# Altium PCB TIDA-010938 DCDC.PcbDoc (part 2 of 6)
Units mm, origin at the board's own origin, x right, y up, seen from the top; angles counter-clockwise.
Board outline 280 x 174.95 mm, 4 copper layers (Top Layer, Layer 1, Layer 2, Bottom Layer), stack 1.787 mm thick; 409 components, 218 nets, 1371 pads, 2268 vias.
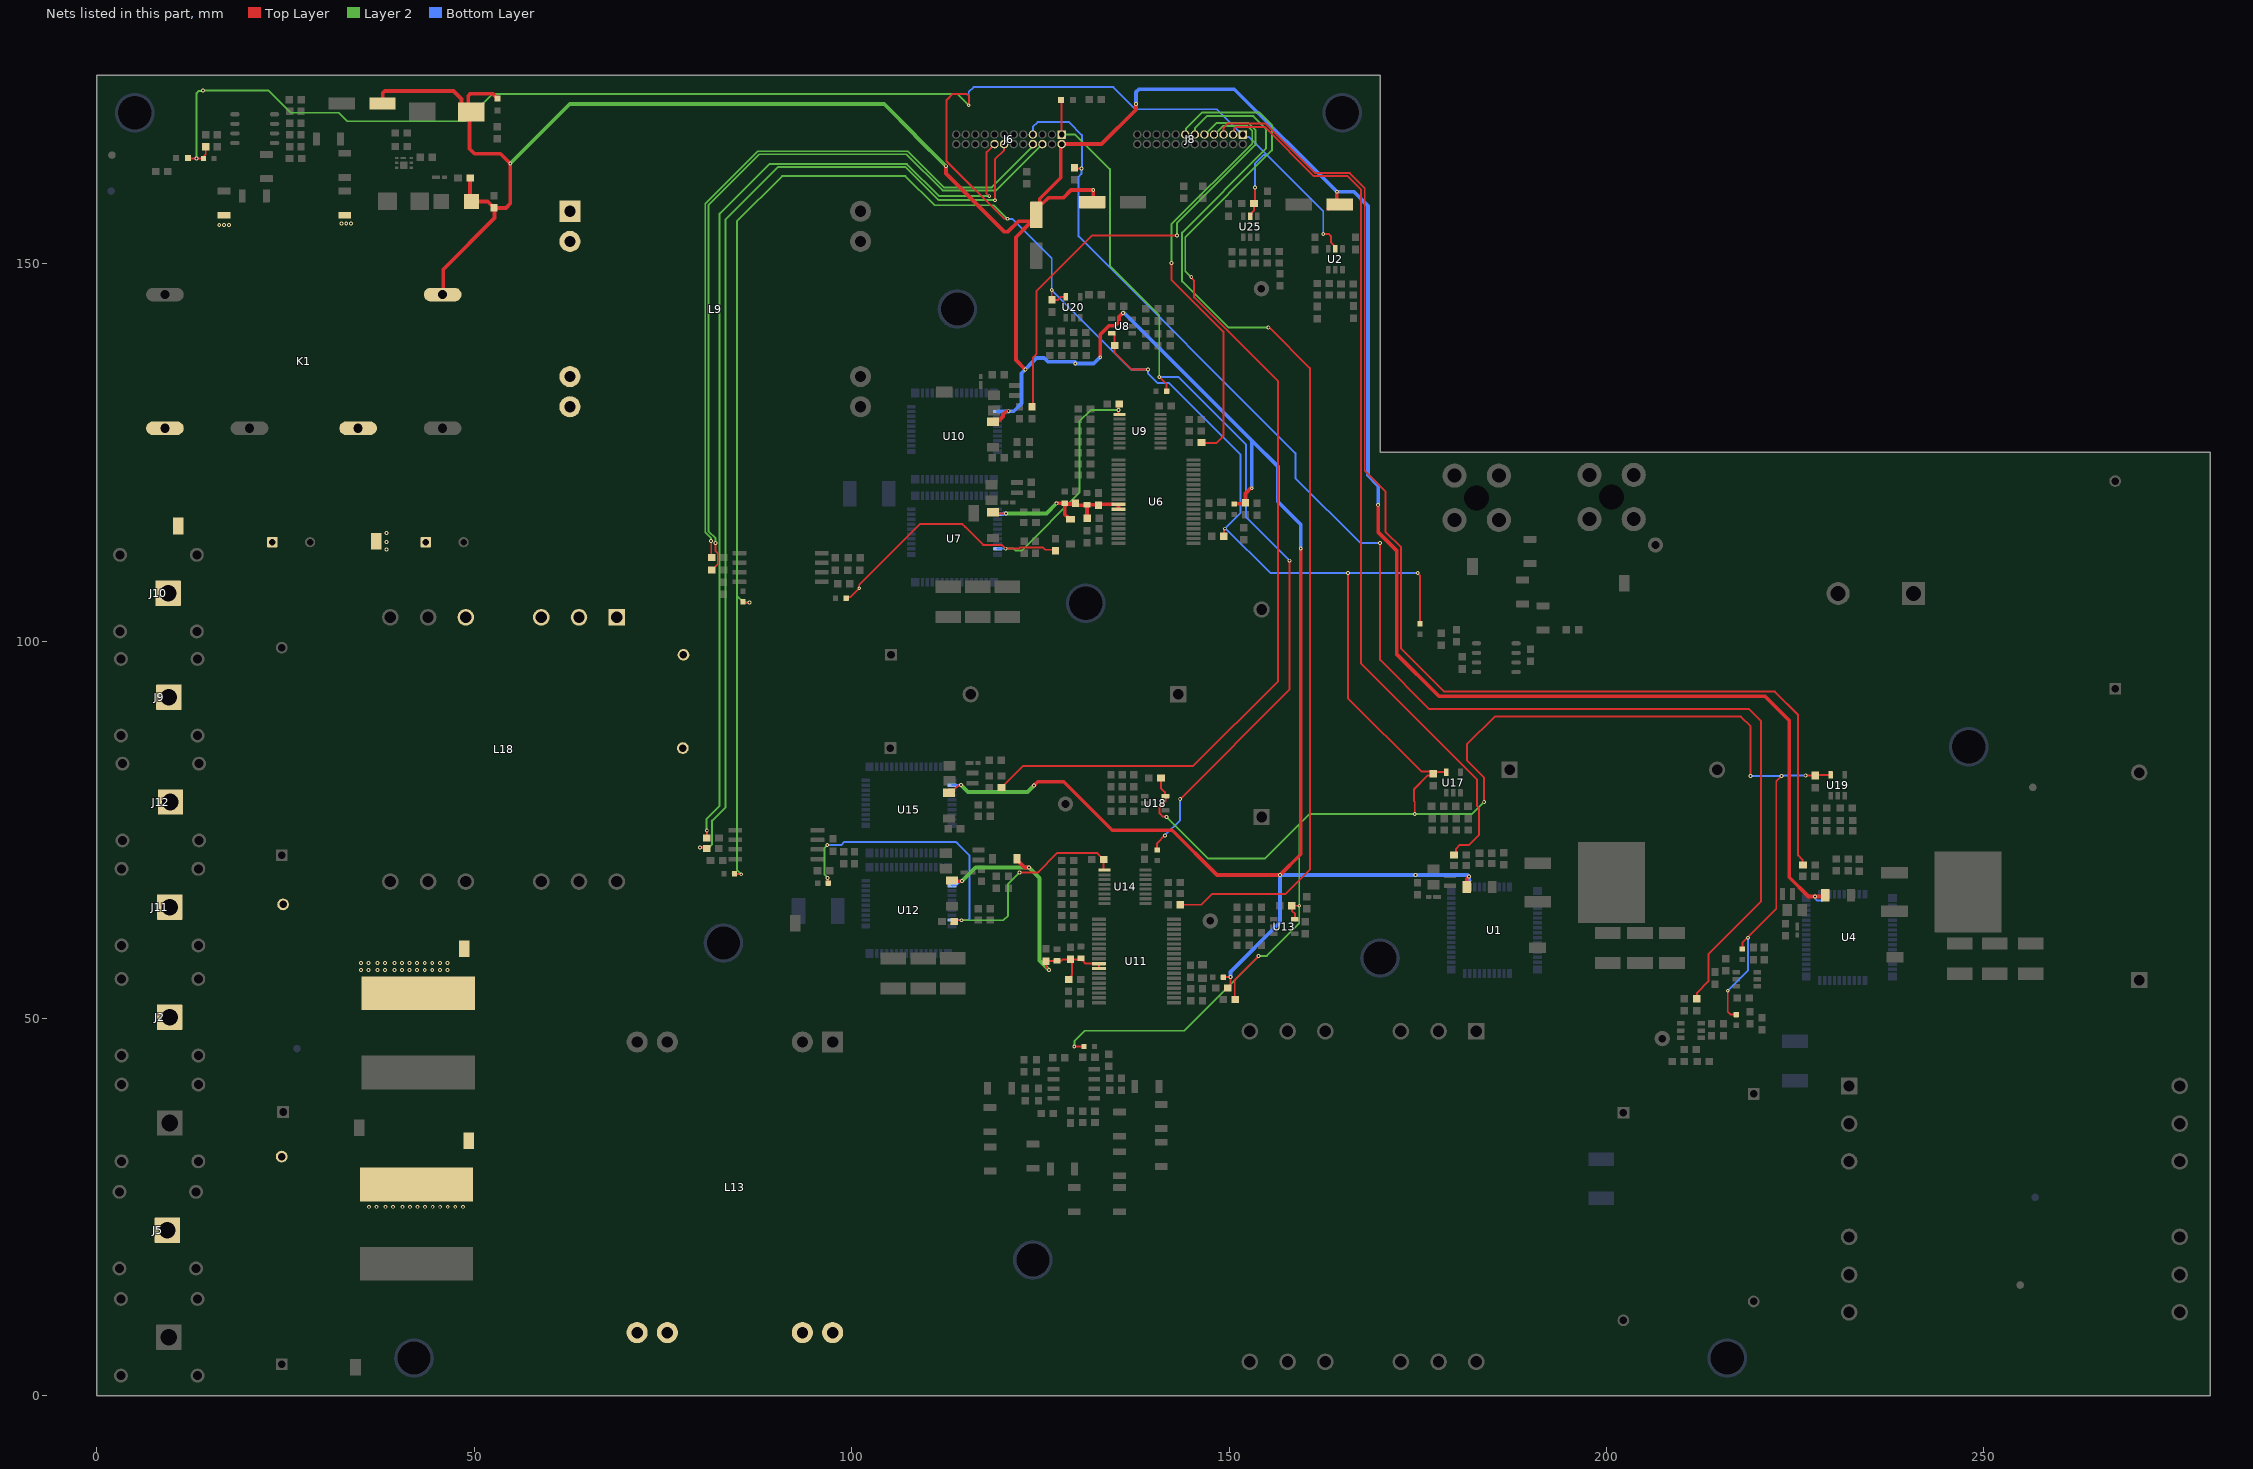
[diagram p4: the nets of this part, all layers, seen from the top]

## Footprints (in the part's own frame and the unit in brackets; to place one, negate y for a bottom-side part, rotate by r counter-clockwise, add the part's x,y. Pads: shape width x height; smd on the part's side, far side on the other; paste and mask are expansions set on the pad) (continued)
FP-CSS2H-2512K-3L00F_2512-MFG [mm]
  rrect6% 1.8x3.4 smd paste+0 mask+0: 1(-2.6,0) 2(2.6,0)
  silkscreen extent -1.33,-1.63 1.33,1.63, body extent -3.17,-1.53 3.17,1.53, height 0.81
FP-FCR7350B_CONN_BANANA_JACK-MFG [mm]
  rrect3% 3.35x3.35 hole 2.2 paste-2539.97 mask+0: 1(11,0)
  round 1.85 hole 1.2 paste-2539.97 mask+0: 2(4.64,5.08) 3(14.8,5.08) 4(4.64,-5.08) 5(14.8,-5.08)
  silkscreen extent 5.94,-6.05 17.2,6.05, body extent -16.7,-6.15 16.7,6.15, height 0.25
FP-FCR7350R_CONN_BANANA_JACK-MFG [mm]
  rrect3% 3.35x3.35 hole 2.2 paste-2539.97 mask+0: 1(11,0)
  round 1.85 hole 1.2 paste-2539.97 mask+0: 2(4.64,5.08) 3(14.8,5.08) 4(4.64,-5.08) 5(14.8,-5.08)
  silkscreen extent 5.94,-6 17.22,6, body extent -16.6,-6.1 16.6,6.1, height 0.25
"FP-G7L-2A-X DC12_PTH_RELAY_52MM5_35MM5-MFG" [mm]
  rrect100% 5x1.8 hole 1.2 slot 4.4 at 0 deg paste-1000 mask+0: 0(18.4,9.1) 1(-18.4,9.1) 2(18.4,-8.6) 4(7.2,-8.6) 6(-7.2,-8.6) 8(-18.4,-8.6)
  silkscreen extent -26.97,-17.75 26.25,17.75, body extent -26.35,-17.85 26.35,17.85, height 0.25
"FP-KG DELLS1.22-JGKH-24_0603-MFG" [mm]
  rrect20% 1.05x0.5 smd paste-1000 mask+0: 1(-0.47,0)
  rrect20% 0.7x0.5 smd paste-1000 mask+0: 2(0.645,0)
  silkscreen extent -1.67,-0.63 0.75,0.63, body extent -1.09,-0.55 1.09,0.55, height 0.25
FP-MH1608-601Y_0603-MFG [mm]
  rrect14% 0.7x0.7 smd paste+0 mask+0: 1(-0.7,0) 2(0.7,0)
  silkscreen extent -0.87,-0.8 0.87,0.8, body extent -1.15,-0.6 1.15,0.6, height 0.25
FP-PTCEL13R102SBE_RADIAL-MFG [mm]
  rrect7% 1.35x1.35 hole 0.85 paste-2539.97 mask+0: 1(-2.5,0)
  round 1.35 hole 0.85 paste-2539.97 mask+0: 2(2.5,0)
  silkscreen extent -6.75,-3.5 6.75,3.5, body extent -6.85,-3.6 6.85,3.6, height 0.25
FP-R533R456050P0M_RADIAL-MFG [mm]
  rrect6% 1.55x1.55 hole 1 paste-2539.97 mask+0: 1(-13.75,0)
  round 1.55 hole 1 paste-2539.97 mask+0: 2(13.75,0)
  silkscreen extent -16.25,-8.15 16.25,8.15, body extent -16.35,-8.25 16.35,8.25, height 0.25
FP-SDEM20161T-4R7MS_SMD2-MFG [mm]
  rrect15% 0.65x1.6 smd paste+0 mask+0: 1(-0.675,0) 2(0.675,0)
  silkscreen extent -1.05,-1.22 1.05,1.2, body extent -1.15,-0.95 1.15,0.95, height 0.25
FP-SHF-112-01-L-D-TH_HDR24-MFG [mm]
  rrect9% 1.12x1.12 hole 0.74 paste-2539.97 mask+0: 1(-6.985,-0.89)
  round 1.12 hole 0.74 paste-2539.97 mask+0: 2(-6.985,0.38) 3(-5.715,-0.89) 4(-5.715,0.38) 5(-4.445,-0.89) 6(-4.445,0.38) 7(-3.175,-0.89) 8(-3.175,0.38) 9(-1.905,-0.89) 10(-1.905,0.38) 11(-0.635,-0.89) 12(-0.635,0.38) 13(0.635,-0.89) 14(0.635,0.38) 15(1.905,-0.89) 16(1.905,0.38) 17(3.175,-0.89) 18(3.175,0.38) 19(4.445,-0.89) 20(4.445,0.38) 21(5.715,-0.89) 22(5.715,0.38) 23(6.985,-0.89) 24(6.985,0.38)
  silkscreen extent -10.86,-3.46 10.86,2.86, body extent -10.96,-2.96 10.96,2.96, height 0.25
FP-SMBJ5350B-TP_SMB-MFG [mm]
  rrect4% 2.5x2.3 smd paste+0 mask+0: 1(-2.15,0) 2(2.15,0)
  silkscreen extent -4.12,-1.97 2.42,1.97, body extent -3.5,-2.07 3.5,2.07, height 0.25
FP-SRP1513CA-220M_SMD2-MFG [mm]
  rrect2% 4.5x15 smd paste+0 mask+0: 1(-5.25,0) 2(5.25,0)
  silkscreen extent -7.9,-8.4 7.9,8.4, body extent -8,-8.5 8,8.5, height 0.25
FP-ZRB18AR61E106ME01L_0603-MFG [mm]
  rrect13% 0.75x0.9 smd paste+0 mask+0: 1(-0.775,0) 2(0.775,0)
  silkscreen extent 0,-0.5 0,0.5, body extent -1.25,-0.6 1.25,0.6, height 0.25
Harwin_S2751-46R [mm] "Test Point, SMT"
  rect 2.2x1.4 smd: 1(0,0)
  body extent -1,-0.6 1,0.6, height 1.4
IEC_HighVoltage_Small [mm]
  silkscreen extent -2.72,-2.24 2.72,2.47
IEC_HotSurface_Small [mm]
  silkscreen extent -2.72,-2.36 2.72,2.35
Keystone5001 [mil] "For Keystone 500x miniature loop terminals"
  round 80 hole 40: 1(0,0)
  silkscreen extent -52,-52 52,52, body extent -49,-49 49,49, height 182
Label_650x200 [mil] "Thermal Transfer Label"
  round 1 on Mech13: 0(0,0)
  silkscreen extent -325,-100 325,100, body extent -325,-100 325,100, height 1
RQS0052C-C01-MFG [mm]
  rrect9% 1.15x1.1 smd paste+0 mask+0: 1(-5.725,5.2) 16(-5.725,-5.2) 27(5.725,-5.2) 42(5.725,5.2)
  rrect22% 1.15x0.45 smd paste+0 mask+0: 2(-5.725,4.225) 3(-5.725,3.575) 4(-5.725,2.925) 5(-5.725,2.275) 6(-5.725,1.625) 7(-5.725,0.975) 8(-5.725,0.325) 9(-5.725,-0.325) 10(-5.725,-0.975) 11(-5.725,-1.625) 12(-5.725,-2.275) 13(-5.725,-2.925) 14(-5.725,-3.575) 15(-5.725,-4.225) 28(5.725,-4.225) 29(5.725,-3.575) 30(5.725,-2.925) 31(5.725,-2.275) 32(5.725,-1.625) 33(5.725,-0.975) 34(5.725,-0.325) 35(5.725,0.325) 36(5.725,0.975) 37(5.725,1.625) 38(5.725,2.275) 39(5.725,2.925) 40(5.725,3.575) 41(5.725,4.225)
  rrect15% 0.665x1.15 smd paste+0 mask+0: 17(-2.043,-5.725) 52(-2.043,5.725)
  rrect22% 0.45x1.15 smd paste+0 mask+0: 18(-1.285,-5.725) 19(-0.635,-5.725) 20(0.015,-5.725) 21(0.665,-5.725) 22(1.315,-5.725) 23(1.965,-5.725) 24(2.615,-5.725) 25(3.265,-5.725) 26(3.915,-5.725) 43(3.915,5.725) 44(3.265,5.725) 45(2.615,5.725) 46(1.965,5.725) 47(1.315,5.725) 48(0.665,5.725) 49(0.015,5.725) 50(-0.635,5.725) 51(-1.285,5.725)
  silkscreen extent -7.02,-6.05 4.77,6.05, body extent -6,-6 6,6, height 1
SM_RADIAL_8MM [mm] "Nichicon 8x10"
  rect 3.5x2.5 smd: 1(-3.25,0) 2(3.25,0)
  silkscreen extent -4.25,-4.25 4.25,4.25, body extent -4.25,-4.25 4.25,4.25, height 10.5
SMA [mm] "Molded Diode, 2-Leads, Body 4.3x2.6mm, IPC Medium Density, based on OnSemi component dimensions and land pattern"
  rect 2x2 smd: 1(-2,0) 2(2,0)
  silkscreen extent -3.66,-1.57 2.79,1.58, body extent -2.6,-1.3 2.6,1.3, height 2.42
SOD-123 [mm] "On Semi recommended land pattern"
  rect 0.915x1.22 smd: 1(-1.637,0) 2(1.637,0)
  silkscreen extent -2.74,-1.17 2.03,1.17, body extent -1.93,-0.9 1.93,0.9, height 1.35
TNPV1206 [mm] "VISHAY"
  rrect11% 0.9x1.7 smd: 1(-1.6,0) 2(1.6,0)
  silkscreen extent -2.4,-1.2 2.4,1.2, body extent -1.67,-0.87 1.67,0.87, height 0.65
UWT_630x770 [mm] "SMD, 2-Leads, Dia 6.3mm"
  rrect6% 3.5x1.6 smd: 1(-2.7,0) 2(2.7,0)
  body extent -3.5,-3.3 3.5,3.3, height 8
WEEE_Minimum [mm] "WEEElie bin"
  silkscreen extent -2.42,-4.38 2.52,2.65
WL-SMCW_GREEN [mm] "WURTH"
  rect 0.8x0.8 smd: 1(-0.8,0) 2(0.8,0)
  silkscreen extent -1.9,-0.8 1.2,0.8, body extent -0.85,-0.45 0.85,0.45, height 0.8
Wurth_WP-THRBU [mm] "Power Element Bush, M3, TH"
  round 3.2 hole 1.85: 1(-2.935,-2.935) 1(-2.935,2.935) 1(2.935,-2.935) 1(2.935,2.935)
  round 3.1 on Top Paste: ""(-2.935,-2.935) ""(-2.935,2.935) ""(2.935,-2.935) ""(2.935,2.935)
  round 3 hole 3.3 unplated mask+0.102: ""(0,0)
  silkscreen extent -3.5,-3.5 3.5,3.5, body extent -3.5,-3.5 3.5,3.5, height 3

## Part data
C1 C8 C21 C31 C36 C37 C43 C48 C49 C50 C51 C52 C56 C57 C61 C70 C71 C77 C84 C85 C95 C102 C107 C108 C119 C124 C125 C128 C129 C132 C146 C155: library part CMP-0006752-5, "CAP, CERM, 0.1 uF, 25 V, +/- 5%, X7R, 0603", Cap_Case=0603, Manufacturer=AVX, Supplier Part Number 1=478-3713-1-ND, TempCo=X7R, Tolerance_%=5%, Value1="0.05 ohm", Value2=25V, ValueDisplayed=0.1uF
C2 C30 C224: library part CMP-0045188-1, "5.6 µF Film Capacitor 310V 630V Polypropylene (PP), Metallized Radial", Digikey Part Number=399-R533R456050P0M-ND, Manufacturer=KEMET, Mouser Part Number=80-R533R456050P0M, Operating Temperature Range="-40°C to +110°C", Tolerance_%=20%, ValueDisplayed=5.6uF, Voltage Ac Rating X=310V
C3 C4 C10 C24: library part CMP-0045062-1, "2.7 µF Film Capacitor 900V Polypropylene (PP), Metallized Radial", Digikey Part Number=399-C4AKOBU4270A3YJ-ND, Manufacturer=Kemet, Mouser Part Number=80-C4AKOBU4270A3YJ, Operating Temperature Range="-55°C to +135°C", Tolerance_%=5%, ValueDisplayed=2.7uF
C5 C115 C121 C144: library part CMP-0081462-1, "CAP, AL, 100 µF, 25 V, +/- 20%, SMD", Cap_Case=6.3x7.7mm, Manufacturer=Nichicon, Supplier Part Number 1=493-2190-1-ND, Tolerance_%=20%, Value2=25V, ValueDisplayed=100µF
C6 C20 C34 C59 C68 C93: library part CMP-0750154-1, "CAP, CERM, 10 µF, 25 V,+/- 10%, X7R, AEC-Q200 Grade 1, 1206", Cap_Case=1206, Manufacturer="Taiyo Yuden", TempCo=X7R, Tolerance_%=10%, Value2=25V, ValueDisplayed=10µF
C7 C11 C12 C14 C15 C19 C22 C25 C26 C28 C29 C35 C45 C54 C55 C58 C62 C64 C69 C79 C88 C89 C90 C92 C96 C98 C112 C116 C118 C120 C122 C142 C151 C152: library part CMP-0007442-5, "CAP, CERM, 220 pF, 50 V, +/- 10%, X7R, 0603", Cap_Case=0603, Manufacturer=MuRata, Supplier Part Number 1=490-1483-1-ND, TempCo=X7R, Tolerance_%=10%, Value1=Unknown, Value2=50V, ValueDisplayed=220pF
C9 C23: library part CMP-0045101-1, "6 µF Film Capacitor 700V Polypropylene (PP), Metallized Radial", Digikey Part Number=399-C4AUJBU4600M18J-ND, Manufacturer=KEMET, Mouser Part Number=80-C4AUJBU4600M18J, Operating Temperature Range="-55°C to +105°C", Tolerance_%=5%, ValueDisplayed=6uF
C13 C27 C46 C65 C80 C99: library part CMP-0007975-2, "CAP, CERM, 2.2 uF, 25 V, +/- 10%, X7R, AEC-Q200 Grade 1, 0805", Cap_Case=0805, Manufacturer=TDK, Supplier Part Number 1=445-6965-1-ND, TempCo=X7R, Tolerance_%=10%, Value1=Unknown, Value2=25V, ValueDisplayed=2.2uF
C16: library part CMP-0007470-5, "CAP, CERM, 0.1 uF, 100 V, +/- 10%, X7R, 0603", Cap_Case=0603, Manufacturer=MuRata, Supplier Part Number 1=490-6439-1-ND, TempCo=X7R, Tolerance_%=10%, Value1=Unknown, Value2=100V, ValueDisplayed=0.1uF
C17 C32 C38 C72: library part CMP-0086152-1, "CAP, CERM, 1 µF, 25 V,+/- 10%, X5R, 0603", Cap_Case=0603, Manufacturer="Taiyo Yuden", TempCo=X5R, Tolerance_%=10%, Value2=25V, ValueDisplayed=1µF
C18 C33 C44 C47 C53 C81: library part CMP-0750039-1, "CAP, CERM, 0.01 µF, 50 V,+/- 10%, X7R, 0603", Cap_Case=0603, Manufacturer="Wurth Elektronik", TempCo=X7R, Tolerance_%=10%, Value2=50V, ValueDisplayed=0.01µF
C39 C73: library part CMP-0009474-2, "CAP, CERM, 20 uF, 16 V, +/- 20%, X5R, 0704", Cap_Case=0704, Manufacturer=MuRata, TempCo=X5R, Tolerance_%=20%, Value1=Unknown, Value2=16V, ValueDisplayed=20uF
C40 C41 C74 C75: library part CMP-0094458-1, "10µF ±20% 25V Ceramic Capacitor X5R 0603 (1608 Metric)", Digikey Part Number=490-10991-1-ND, Manufacturer="Murata Electronics", Mouser Part Number=81-ZRB18AR61E106ME1L, Operating Temperature Range="-55°C to +85°C", Temperature Characteristic=X5R, Tolerance_%=20%, ValueDisplayed=10uF
C42 C76: library part CMP-0007209-4, "CAP, CERM, 330 pF, 50 V, +/- 5%, C0G/NP0, 0603", Cap_Case=0603, Manufacturer=MuRata, Supplier Part Number 1=490-1439-1-ND, TempCo=C0G/NP0, Tolerance_%=5%, Value1=Unknown, Value2=50V, ValueDisplayed=330pF
C60 C94: library part CMP-0045063-1, "2.4 µF Film Capacitor 700V Polypropylene (PP), Metallized Radial", Digikey Part Number=399-C4AUJBU4240M1WJ-ND, Manufacturer=KEMET, Mouser Part Number=80-C4AUJBU4240M1WJ, Operating Temperature Range="-55°C to +105°C", Tolerance_%=5%, ValueDisplayed=2.4uF
C63 C66 C103 C104 C105 C109 C123: library part CMP-0007189-4, "CAP, CERM, 1600 pF, 50 V, +/- 5%, C0G/NP0, 0603", Cap_Case=0603, Manufacturer=MuRata, Supplier Part Number 1=490-1456-1-ND, TempCo=C0G/NP0, Tolerance_%=5%, Value1=Unknown, Value2=50V, ValueDisplayed=1600pF
C67 C78 C82 C83 C86 C87 C91 C97: library part CMP-0006920-4, "CAP, CERM, 330 pF, 50 V, +/- 5%, C0G/NP0, 0603", Cap_Case=0603, Manufacturer=Kemet, Supplier Part Number 1=399-1068-1-ND, TempCo=C0G/NP0, Tolerance_%=5%, Value1=Unknown, Value2=50V, ValueDisplayed=330pF
C100 C101 C106 C110 C111 C113 C127 C130 C131 C135 C140 C141: library part CMP-0009326-2, "0.03 µF ±10% 1000V (1kV) Ceramic Capacitor C0G, NP0 1812 (4532 Metric)", Cap_Case=1812, Manufacturer=Kemet, Supplier Part Number 1=399-C1812C303KDGLCAUTOTR-ND, TempCo=NP0, Tolerance_%=10%, Value1=Unknown, Value2=1000V, ValueDisplayed=0.03uF
C114: library part CMP-0033686-1, "ALH82, Aluminum Electrolytic, 160 uF, 20%, 600 VDC, -40/+105°C", Leakage Current=288uA, Manufacturer=KEMET, Operating Temperature Range="-40°C to +105°C", Tolerance_%=20%, ValueDisplayed=160uF
C117: library part CMP-0012113-3, "CAP, Aluminum Polymer, 10 uF, 25 V, +/- 20%, 0.06 ohm, 8x10 SMD", Cap_Case=8.3x8.3x6.9, Manufacturer=Panasonic, Tolerance_%=20%, Value1="0.06 ohm", Value2=25V, ValueDisplayed=10uF
C143: library part CMP-0123402-1, "15 µF Film Capacitor 600V Polypropylene (PP), Metallized Radial", Digikey Part Number=399-C4AQHBU5150P12J-ND, Manufacturer=KEMET, Mouser Part Number=80-C4AQHBU5150P12J, Operating Temperature Range="-55°C to +125°C", Tolerance_%=5%, ValueDisplayed=15uF
D1 D3: library part CMP-0042032-1, "Schottky Diode 650 V 20A Surface Mount TO-263-2", Digikey Part Number=1697-C6D20065G-ND, Forward Current=64A, Manufacturer=Wolfspeed, Max Surge Forward Current=135A, Mouser Part Number=941-C6D20065G, Operating Temperature Range="-55°C to +175°C", Peak Reverse Current=5uA, ValueDisplayed=1153pF
D6 D9: library part CMP-0005769-4, "Diode, Zener, 16 V, 500 mW, AEC-Q101, SOD-123", Manufacturer="Diodes Inc.", Power_W=500mW, Value1=0.5W
D11: library part CMP-0097215-1, "Zener Diode 13 V 5 W ±5% Surface Mount DO-214AA (SMB)", Digikey Part Number=SMBJ5350B-TPMSCT-ND, Manufacturer=MCC, Max Reverse Leakage Current=1uA, Mouser Part Number=833-SMBJ5350B-TP, Operating Temperature Range="-55°C to +150°C", Power_W=5W
D12: library part CMP-0029023-2, "Diode, Superfast Rectifier, 150 V, 1 A, SMA", Manufacturer="Diodes Inc.", Value1=1A, Value2=0.92V
D13 D15 D16: library part CMP-0002894-2, "LED, Green, SMD", Color=green, Manufacturer="Wurth Elektronik", Value1=W, Value2=2V
D14 D17 D18 D19 D20 D21 D22: library part CMP-0093310-1, "Standard LEDs - SMD Green TOPLED E 1608", Color=Green, Forward Current=2mA, Manufacturer="Osram Opto", Mouser Part Number=720-KGDELLS122A4849, Operating Temperature Range="-40°C to +110°C"
FB1 FB2 FB3 FB4 FB5 FB6 FB7 FB9 FB10 FB11 FB12 FB13 FB14: library part CMP-0037505-1, "600 Ohms @ 100 MHz 1 Power, Signal Line Ferrite Bead 0603 (1608 Metric) 1A 200mOhm", Digikey Part Number=MH1608-601YCT-ND, Impedance At Frequency="600Ω @ 100MHz", Manufacturer=Bourns, Mouser Part Number=652-MH1608-601Y, Operating Temperature Range="-55°C to +125°C", Test Frequency=100MHz, Tolerance_%=25%
FID1 FID2 FID3 FID4 FID5 FID6: library part CMP-0077181-1, "Fiducial mark.  There is nothing to buy or mount.", Manufacturer=N/A
J1 J4: library part CMP-0078526-1, "Power Element Bush, M3, TH", Current_A=50A, Manufacturer="Wurth Elektronik", Supplier Part Number 1=732-10882-1-ND
J2 J5 J9 J10: library part CMP-0032022-2, "Banana Jack Connector Standard Banana Solder Red", Current_A=24A, Digikey Part Number=4654-FCR7350R-ND, Manufacturer="CLIFF Electronic Components", Operating Temperature Range="-40°C to +80°C", Voltage_V=1kV
J3 J7 J11 J12: library part CMP-0032021-2, "Banana Jack Connector Standard Banana Solder Black", Current_A=24A, Digikey Part Number=4654-FCR7350B-ND, Manufacturer="CLIFF Electronic Components", Operating Temperature Range="-40°C to +80°C", Voltage_V=1kV
J6 J8: library part CMP-0003796-1, "Conn Shrouded Header (4 Sides) HDR 24 POS 1.27mm Solder ST Top Entry Thru-Hole Tube", Digikey Part Number=SHF-112-01-L-D-TH-ND, Manufacturer=Samtec, Mouser Part Number=200-SHF11201LDTH, Operating Temperature Range="-55°C to +125°C"
K1: library part CMP-0093885-1, "General Purpose Relay DPST-NO (2 Form A) 12VDC Coil Through Hole", Coil Current_A=191.7mA, Coil Power_W=2.3W, Coil Resistance=63Ω, Coil Voltage_VDC=12V, Contact Rating_A=30A, Digikey Part Number=Z6085-ND, Manufacturer=Omron, Mouser Part Number=653-G7L2AXDC12, Operating Temperature Range="-40°C to +85°C"
L1 L4: library part CMP-0123113-1, "PFC Inductor 120uH", Manufacturer=Bourns, Operating Temperature Range="-40°C to +125°C", Test Frequency=100kHz, Tolerance_%=10%
L2 L5 L7 L10 L11 L14: library part CMP-0089347-1, "4.7µH Unshielded Inductor 1.1A 426mOhm Max 0806 (2016 Metric)", Digikey Part Number=2037-SDEM20161T-4R7MSCT-ND, Manufacturer=Cyntec, Operating Temperature Range="-55°C to +125°C", Test Frequency=1MHz, Tolerance_%=20%
L6 L8: library part CMP-0095753-1, "22 µH Shielded Inductor 17 A 13.86mOhm Max Nonstandard", Digikey Part Number=118-SRP1513CA-220MCT-ND, Manufacturer=Bourns, Mouser Part Number=652-SRP1513CA-220M, Operating Temperature Range="-55°C to +155°C", Self Resonant Frequency=6MHz, Test Frequency=100kHz, Tolerance_%=20%
L9 L13: library part CMP-0123019-1, "Inductor", Manufacturer=Bourns, Operating Temperature Range="-40°C to +125°C", Test Frequency=100kHz, Tolerance_%=10%
L18: library part CMP-0123020-1, "Inductor 22 μH 10% 5mΩ", Manufacturer=Bourns, Operating Temperature Range="-40°C to +125°C", Test Frequency=100kHz, Tolerance_%=10%
LBL1: library part CMP-0003625-1, "Thermal Transfer Printable Labels, 0.650\" W x 0.200\" H - 10,000 per roll", Manufacturer=Brady, Supplier Part Number 1=97C5133
LOGO1: library part CMP-0074837-1, "IEC 61010-1 Hot Surface Warning"
Logo2: library part CMP-0074844-1
Logo3: library part CMP-0074847-1, "FCC_disclaimer"
Logo4: library part CMP-0074769-1
LOGO5: library part CMP-0074835-1, "IEC 61010-1 High Voltage Warning"
MP1 MP2 MP3 MP4 MP5 MP6 MP7 MP8 MP9 MP11: library part CMP-0040203-1, "Round Spacer Unthreaded Steel 0.059\" (1.50mm)", Digikey Part Number=732-7071-1-ND, Manufacturer="Wurth Electronics", Mouser Part Number=710-9774015960R, Operating Temperature Range="-55°C to +150°C"
Q1: library part CMP-0076725-1, "30-V N-Channel NexFET™ Power MOSFET", Manufacturer="Texas Instruments"
R1 R3 R4 R5 R8 R11 R13 R14 R15 R19 R24 R34 R35 R37 R38 R40 R46 R49 R51 R59 R60 R61 R62 R63 R65 R66 R72 R73 R75 R76 R77 R78 R83 R84 R85 R86 R87 R89 R95 R99 R108 R109 R112 R113 R116 R117 R120 R121 R146 R149 R150 R151 R152 R155 R158 R159: library part CMP-0023572-3, "RES, 56, 0.1%, 0.1 W, 0603", Manufacturer="Susumu Co Ltd", Power_W=100mW, Supplier Part Number 1=RG16P56.0BCT-ND, TempCo="25 ppm/C", Tolerance_%=0.1%, Value2=0.1W, Value_Code=56R0, ValueDisplayed=56
R2 R88: library part CMP-0043438-1, "PTCEL Series 850 V 1 kOhm ±30 % Radial Inrush Current Limiter PTC Thermistor", Digikey Part Number=56-PTCEL13R102SBE-ND, Hold Current=30mA, Manufacturer=Vishay, Max Current=40A, Mouser Part Number=594-PTCEL13R102SBE, Operating Temperature Range="-40°C to +105°C", Tolerance_%=30%
R6 R16 R32 R45 R57 R70: library part CMP-0022906-5, "RES, 20.0 k, 1%, 0.1 W, 0603", Manufacturer=Yageo, Power_W=100mW, Supplier Part Number 1=311-20.0KHRCT-ND, TempCo="100 ppm/C", Tolerance_%=1%, Value2=0.1W, Value_Code=20k0, ValueDisplayed=20.0k
R7 R147: library part CMP-0024836-3, "RES, 1.67 k, 0.5%, 0.1 W, 0603", Manufacturer="Yageo America", Power_W=100mW, TempCo="50 ppm/C", Tolerance_%=0.5%, Value2=0.1W, Value_Code=1k67, ValueDisplayed=1.67k
R9 R10 R20 R56 R58 R67 R71 R96: library part CMP-0023661-3, "RES, 10.0, 0.1%, 0.1 W, 0603", Manufacturer="Yageo America", Power_W=100mW, TempCo="25 ppm/C", Tolerance_%=0.1%, Value2=0.1W, Value_Code=10R0, ValueDisplayed=10.0
R12 R39 R64 R79 R80 R81 R82 R90 R91 R92 R93 R104 R106 R107 R125 R127 R129 R131 R139 R140 R141 R156 R157: library part CMP-0023404-3, "RES, 10.0 k, 0.1%, 0.1 W, 0603", Manufacturer="Susumu Co Ltd", Power_W=100mW, Supplier Part Number 1=RG16P10.0KBCT-ND, TempCo="25 ppm/C", Tolerance_%=0.1%, Value2=0.1W, Value_Code=10k0, ValueDisplayed=10.0k
R17 R18: library part CMP-0043791-1, "Res Metal Strip 2512 0.003 Ohm 1% 4W ±75ppm/C Pad SMD Automotive T/R", Digikey Part Number=CSS2H-2512K-3L00FCT-ND, Manufacturer=Bourns, Mouser Part Number=652-CSS2H2512K3L00F, Operating Temperature Range="-55°C to +170°C", Power_W=4W, TempCo=75ppm/°C, Tolerance_%=1%
R21 R26 R28 R30 R31 R33 R36 R41 R42 R43 R44 R53 R68 R69 R74 R94 R98 R100 R101 R102 R103: library part CMP-0018815-2, "RES, 560 k, 0.1%, 1 W, 1206", Manufacturer="Vishay Draloric", Power_W=1W, Supplier Part Number 1=541-2316-1-ND, TempCo="25 ppm/C", Tolerance_%=0.1%, Value_Code=560k
R22 R25 R47 R50: library part CMP-0022685-3, "RES, 12.0 k, 1%, 0.1 W, 0603", Manufacturer=Panasonic, Power_W=100mW, Supplier Part Number 1=P12.0KHCT-ND, TempCo="100 ppm/C", Tolerance_%=1%, Value2=0.1W, Value_Code=12k0, ValueDisplayed=12.0k
R23 R48: library part CMP-0025200-2, "RES, 38.8 k, 0.5%, 0.1 W, 0603", Manufacturer="Yageo America", Power_W=100mW, TempCo="50 ppm/C", Tolerance_%=0.5%, Value2=0.1W, Value_Code=38k8, ValueDisplayed=38.8k
R27 R52: library part CMP-0024286-2, "RES, 4.02 k, 0.1%, 0.1 W, 0603", Manufacturer="Yageo America", Power_W=100mW, TempCo="25 ppm/C", Tolerance_%=0.1%, Value2=0.1W, Value_Code=4k02, ValueDisplayed=4.02k
R29 R54 R145: library part CMP-0023404-1, "RES, 10.0 k, 0.1%, 0.1 W, 0603", Manufacturer="Susumu Co Ltd", Power_W=100mW, Supplier Part Number 1=RG16P10.0KBCT-ND, TempCo="25 ppm/C", Tolerance_%=0.1%, Value2=0.1W, Value_Code=10k0, ValueDisplayed=10.0k
R105 R132 R133 R135 R136 R138: library part CMP-0025933-5, "RES, 5.6 k, 5%, 0.1 W, 0603", Manufacturer=Yageo, Power_W=100mW, Supplier Part Number 1=311-5.6KGRCT-ND, TempCo="100 ppm/C", Tolerance_%=5%, Value2=0.1W, Value_Code=5k60, ValueDisplayed=5.6k
R134 R137: library part CMP-0123595-1, "1.5mOhms ±1% 3W Chip Resistor 2512 (6432 Metric) Automotive AEC-Q200, Current Sense Metal Element", Digikey Part Number=118-CSS2H-2512K-1L50FETR-ND, Manufacturer=Bourns, Mouser Part Number=652-CSS2H2512K1L50FE, Operating Temperature Range="-55°C to +170°C", PartNumber=CSS2H-2512K-1L80FE, Power_W=5W, TempCo=75ppm/°C, Tolerance_%=1%
R144: library part CMP-0023627-2, "RES, 1.00 k, 0.01%, 0.063 W, 0603", Manufacturer="Stackpole Electronics Inc", Power_W=63mW, Supplier Part Number 1=RNCF0603TKY1K00CT-ND, TempCo="5 ppm/C", Tolerance_%=0.01%, Value2=0.063W, Value_Code=1k00, ValueDisplayed=1.00k
R153: library part CMP-0082532-1, "RES, 499, 1%, 0.1 W, 0603", Manufacturer=Vishay-Dale, Power_W=100mW, Supplier Part Number 1=541-3986-1-ND, TempCo="100 ppm/C", Tolerance_%=1%, Value2=0.1W, Value_Code=499R, ValueDisplayed=499
R154: library part CMP-0024934-2, "RES, 218, 0.5%, 0.1 W, 0603", Manufacturer="Yageo America", Power_W=100mW, TempCo="50 ppm/C", Tolerance_%=0.5%, Value2=0.1W, Value_Code=218R, ValueDisplayed=218
TP1 TP4 TP5 TP6 TP42: library part CMP-0055138-2, "Test Point, Miniature, Black, TH", Color=Black, Manufacturer="Keystone Electronics", Supplier Part Number 1=36-5001-ND
TP2 TP9 TP10 TP12 TP16 TP35 TP39 TP40 TP41 TP43 TP44 TP45 TP46: library part CMP-0003968-1, "Test Point, SMT", Manufacturer=Harwin, Supplier Part Number 1=952-2664-1-ND
U1 U4 U7 U10 U12 U15: library part CMP-0089967-3, "650-V 30-mΩ GaN FET with Integrated Driver and Protection", Manufacturer="Texas Instruments", Max Supply Voltage=18V, Min Supply Voltage=7.5V, Nominal Supply Current=16mA, Operating Temperature Range="-40°C to +125°C", Output Voltage=520V
U2 U25: library part CMP-0051910-1, "Dual Buffer Gate, DBV0006A, LARGE T&R", F @ Nom Voltage(Max)(Mhz)=150, Generic Part Number=SN74LVC2G34, ICC @ Nom Voltage(Max)(mA)=0.01, Manufacturer="Texas Instruments", Operating Temperature Range(C)="-40 to 125,-40 to 85", Rating=Catalog, tpd @ Nom Voltage(Max)(ns)=8.6,4.4,4.1,3.2, Voltage(Nom)(V)=1.8,2.5,3.3,5
U3 U5: library part CMP-0013232-2, "Bidirectional, Low- and High-Side Measurement, Multichannel, Voltage Output, Current-Sense Amplifier, DBV0006A (SOT-6)", Alternate Manufacturer="Texas Instruments"
U6 U11: library part CMP-0033793-2, "Automotive 1.5-W, 12-V VIN / 12-VOUT, 15-V VIN / 15-V VOUT, HighDensity, > 5-kVRMS, Isolated DC/DC Module", Manufacturer="Texas Instruments", Max Supply Voltage=18V, Min Supply Voltage=9V, Nominal Supply Current=200-270mA, Operating Temperature Range="-40°C to +150°C", Output Voltage=10-18V, Switching Frequency=18MHz
U8 U13 U17 U18 U19 U20: library part CMP-0051571-2, "Single 2-Input Positive-AND Gate, DBV0005A, SMALL T&R", Alternate Manufacturer="Texas Instruments", F @ Nom Voltage(Max)(Mhz)=150, Generic Part Number=SN74LVC1G08, ICC @ Nom Voltage(Max)(mA)=0.01, Operating Temperature Range(C)="-40 to 125,-40 to 85", Rating=Catalog, tpd @ Nom Voltage(Max)(ns)=4.5,6,4,5, Voltage(Nom)(V)=1.8,2.5,3.3,5
U9 U14: library part CMP-0089510-1, "General Purpose Digital Isolator 5000Vrms 4 Channel 100Mbps 85kV/µs CMTI 16-SSOP (0.154\", 3.90mm Width)", Digikey Part Number=296-48140-1-ND, Manufacturer="Texas Instruments", Max Supply Voltage=5.5V, Min Supply Voltage=2.25V, Mouser Part Number=595-ISO7741FDBQR, Nominal Supply Current=0.8-18mA, Operating Temperature Range="-55°C to +125°C"
U16: library part CMP-0097119-1, "Precision, Zero-Drift, Zero-Crossover, True Rail-to-Rail, Input/Output Operational Amplifiers", Digikey Part Number=296-OPA2388IDRCT-ND, Input Bias Current=0.00003uA, Input Offset Voltage=0.00025mV, Manufacturer="Texas Instruments", Max Dual Supply Voltage=2.75V, Max Supply Voltage=5.5V, Min Dual Supply Voltage=1.25V, Min Supply Voltage=2.5V, Mouser Part Number=595-OPA2388IDR, Nominal Supply Current=1.7-1.9mA, Operating Temperature Range="-40°C to +125°C", Output Current Per Channel=30-60mA, Voltage Gain=126-148dB
U21 U22: library part CMP-0080671-1, "Precision Reinforced Isolated Amplifier for Current Sensing, DWV0008A (SOIC-8)", Alternate Manufacturer="Texas Instruments", Alternate PartNumber=AMC1302DWVR
U23 U26: library part CMP-0075798-1, "Precision, Zero-Drift, Zero-Crossover, True Rail-to-Rail Input/Output, Operational Amplifier, D0008A (SOIC-8)", Alternate Manufacturer="Texas Instruments", Alternate PartNumber=OPA388ID
ZZ1: library part CMP-0003616-3
ZZ2: library part CMP-0077236-1
ZZ3: library part CMP-0077237-1
ZZ4: library part CMP-0077238-1

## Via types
v1: diameter 0.508, hole 0.254, Top Layer to Bottom Layer, tented both sides, 1783 vias
v2: diameter 0.508, hole 0.254, Top Layer to Bottom Layer, 485 vias

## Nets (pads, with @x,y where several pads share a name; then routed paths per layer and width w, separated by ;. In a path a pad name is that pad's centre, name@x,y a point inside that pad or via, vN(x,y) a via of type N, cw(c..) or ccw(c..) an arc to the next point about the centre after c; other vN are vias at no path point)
3V3_HVN: C52.1 C119.2 C124.1 C125.1 C128.1 C129.1 C132.2 C146.1 D16.2 FB1.1 FB2.1 FB3.1 FB7.1 FB11.1 FB12.1 FB13.1 J8.1 R22.1 R47.1 U2.5 U8.5 U13.5 U17.5 U18.5 U19.5 U20.5 U25.5 | length 708.3
  Top Layer w0.254: D16.2@12.073,164.013 12.131,163.954 v1(13.189,163.954) FB11.1@14.111,163.954 ; FB11.1@14.111,164.2 14.411,164.5 C132.2@14.411,165.495 ; FB13.1@84.218,69.18 84.259,69.139 85.32,69.139 v1(85.361,69.099) ; FB12.1@85.581,105.208 85.708,105.082 86.43,105.082 v1(86.471,105.123) ; v1(115.5,171) 115.5,172.25 115.25,172.5 113.382,172.5 112.557,171.675 112.557,163.597 120.2,155.955 v1(120.617,155.955) ; v1(126.5,146.5) 126.5,145.253 C129.1@126.55,145.203 127.31,145.203 127.702,145.595 U20.5@128.383,145.595 ; v1(129.479,46.272) FB3.1@130.768,46.272 ; U8.5@134.439,140.785 134.633,140.785 134.806,140.612 C52.1@134.806,139.148 ; C52.1@134.831,139.148 134.831,138.219 137.05,136 v1(139.25,136) ; C125.1@140.977,81.855 140.977,80.523 141.505,79.995 141.505,79.638 141.505,79.533 U18.5@141.576,79.463 ; v1(141.704,76.7) 141.655,76.749 141.228,76.749 140.799,77.178 140.799,77.948 141.56,78.708 141.56,79.29 U18.5@141.733,79.463 ; R22.1@149.32,113.886 149.32,114.708 149.433,114.821 v1(149.433,114.89) v1@149.384,114.938 ; R47.1@150.75,52.5 150.75,55.142 v1(153.904,58.296) ; U25.5@152.805,156.286 152.978,156.459 152.978,156.739 153.302,157.063 153.302,157.919 153.446,158.063 v1(153.446,160.108) ; C146.1@158.3,64.933 158.36,64.872 158.36,64.225 158.746,63.839 158.746,63.037 U13.5@158.805,62.978 ; C146.1@158.573,65.181 158.573,65.032 158.673,64.933 v1(159.3,64.933) ; v1(162.48,153.941) 163.209,153.941 163.478,153.672 163.478,152.816 163.903,152.391 163.903,152.131 U2.5@164.076,151.958 ; v1(165.75,109) 165.75,92.45 175.5,82.7 176.777,82.7 C124.1@177.046,82.431 ; v1(174.6,77.1) 174.6,78.734 174.5,78.834 174.5,80.4 176.3,82.2 176.815,82.2 C124.1@177.046,82.431 ; v1(175,109) 175,108.931 175.3,108.631 FB7.1@175.3,102.3 ; U17.5@178.76,82.628 177.243,82.628 C124.1@177.046,82.431 ; v1(183.8,78.7) 183.8,81.9 181.5,84.2 181.5,86.3 185.2,90 217.803,90 219.1,88.703 v1(219.1,82.135) ; v1(216.071,53.672) 216.071,50.903 216.474,50.5 FB1.1@217,50.5 ; FB2.1@218,59.2 218,60.023 222.5,64.523 222.5,81.435 v1(223.2,82.135) ; v1(226.4,82.2) 227.647,82.2 C128.1@227.66,82.188 227.735,82.263 U19.5@229.69,82.263
  Layer 2 w0.254: v1(13.189,163.954) 13.189,172.618 13.479,172.908 13.995,172.908 v1(14.043,172.956) 22.695,172.956 25.652,169.999 32.023,169.999 33.149,168.873 48.818,168.873 52.436,172.491 114.009,172.491 v1(115.5,171) ; 84.781,106.03 84.781,69.679 v1(85.361,69.099) ; v1(86.471,105.123) 85.689,105.123 84.781,106.03 84.781,155.629 90.761,161.609 107.115,161.609 110.983,157.742 118.83,157.742 v1(120.617,155.955) ; v1@129.5,46.382 129.5,47 130.875,48.375 144.051,48.375 153.904,58.227 v1(153.904,58.296) 155.014,58.296 159.3,62.583 v1(159.3,64.933) 159.3,75.719 ; v1(141.704,76.7) 147.204,71.2 154.781,71.2 159.3,75.719 ; v1(183.8,78.7) 182.2,77.1 v1(174.6,77.1) 160.681,77.1 159.3,75.719
  Bottom Layer w0.254: v1(115.5,171) 115.5,172.761 116.142,173.403 134.664,173.403 137.597,170.47 148.37,170.47 151.291,167.549 151.377,167.549 152.116,166.81 152.602,166.81 155.029,164.382 ; v1(120.617,155.955) 120.666,155.906 121.315,155.906 126.5,150.721 v1(126.5,146.5) 137,136 v1(139.25,136) 139.25,135.5 140.56,134.19 142.06,134.19 151.5,124.75 151.5,116.957 v1(149.433,114.89) ; v1@149.521,114.979 155.5,109 v1(175,109) ; v1(153.446,160.108) 153.446,163.284 154.544,164.382 155.029,164.382 ; v1(162.48,153.941) 162.48,156.932 160.373,159.039 155.029,164.382 ; v1(216.071,53.672) 218.771,56.372 v1(218.771,60.691) ; v1(219.1,82.135) v1(223.2,82.135) 223.233,82.167 226.367,82.167 v1(226.4,82.2)
5V_HVN: D15.2 FB9.1 FB10.1 J6.1 | length 124
  Top Layer w0.254: D15.2@127.707,171.711 127.81,171.608 J6.1@127.81,167.116 ; FB10.1@140.464,72.325 140.464,73.216 v1(141.502,74.253) ; v1@140.75,135 141.723,134.027 FB9.1@141.723,133.117 ; v1(143.52,79.069) 158,93.549 v1(158,110.653)
  Layer 2 w0.254: J6.1@127.81,167.116 129.613,167.116 134.205,162.525 134.205,149.701 140.75,143.155 v1(140.75,135)
  Bottom Layer w0.254: v1@140.75,135 143.25,135 152.25,126 152.25,116.431 158,110.681 v1(158,110.653) ; v1(141.502,74.253) 143.52,76.271 v1(143.52,79.069)
5V_SW1: C36.2 C51.2 FB5.1 U7.51 U9.1 | length 65.2
  Top Layer w0.254: FB5.1@99.263,105.681 99.405,105.823 99.823,105.823 v1(101,107) 101,107.491 109.009,115.5 114.66,115.5 115.023,115.137 116.037,114.123 117.41,112.75 119.871,112.75 120.377,112.244 122.117,112.244 122.266,112.392 125.353,112.392 125.645,112.1 126.857,112.1 C36.2@127,111.957 ; U9.1@134.868,130.115 134.946,130.037 U9.1@135.493,130.037 135.417,130.037 135.339,130.115 135.339,131.321 C51.2@135.449,131.431
  Layer 2 w0.254: v1(120.397,112.244) 121.474,112.244 121.717,112 122.5,112 130.177,119.677 130.177,129.104 131.672,130.6 v1(135.339,130.6)
  Bottom Layer w0.254: U7.51@119.333,112.244 v1(120.397,112.244)
5V_SW2: C70.2 C85.2 FB14.1 U12.51 U14.1 | length 63.9
  Top Layer w0.254: v1(96.8,68.6) 96.846,68.554 96.846,67.969 FB14.1@96.891,67.923 ; C70.2@113.537,62.863 C70.2@113.562,62.863 113.708,63.009 v1(114.525,63.009) ; v1(122.211,69.337) 124.626,69.337 127.191,71.902 132.539,71.902 133.222,71.219 133.376,71.219 133.376,69.735 133.444,69.668 U14.1@133.491,69.668
  Layer 2 w0.254: v2(96.759,72.98) 96.4,72.62 96.4,69.069 96.8,68.669 v1(96.8,68.6) ; v1(114.525,63.009) 120.097,63.009 120.711,63.623 120.711,67.836 v1(122.211,69.337)
  Bottom Layer w0.254: v2(96.759,72.98) 98.616,72.98 99.037,73.4 113.8,73.4 113.98,73.22 113.993,73.22 115.597,71.616 115.597,63.222 115.384,63.009 v1(114.525,63.009) 114.51,63.024 113.302,63.024 U12.51@113.287,63.039
12V_HVN: C1.2 C5.1 C6.1 C20.1 C59.1 C93.1 C115.1 C117.1 C121.1 C144.1 D12.1 D13.2 FB4.1 FB6.1 J6.2 K1.0 R7.1 R25.1 R50.1 U1.44 U4.44 U10.44 U15.44 | length 606.6
  Top Layer w0.254: C93.1@112.887,79.897 113.137,79.897 113.802,80.562 113.861,80.562 114.164,80.865 114.446,80.865 v1(114.494,80.914) ; FB6.1@149.237,55.46 149.255,55.478 150.161,55.478 v1(150.178,55.495) 150.178,54.38 149.83,54.032 R50.1@149.812,54.032
  Top Layer w0.5: C121.1@37.825,171.248 37.848,171.271 37.848,172.583 38.141,172.876 47.25,172.876 48.314,171.812 48.314,171.105 48.475,170.944 C117.1@49.182,170.944 ; K1.0@45.891,146.05 45.891,149.279 52.673,156.061 C1.2@52.673,156.939 ; C117.1@49.366,170.105 49.366,165.238 50.038,164.566 53.443,164.566 v1(54.749,163.26) 54.749,157.963 54.187,157.4 C1.2@52.616,157.4 52.616,157.425 51.779,158.262 D12.1@49.619,158.262 49.432,158.448 R7.1@49.432,161.36 ; C117.1@49.429,170.271 49.182,170.518 C117.1@49.182,170.944 ; C117.1@49.595,170.105 49.595,170.531 C117.1@49.182,170.944 ; D13.2@53.036,171.897 52.401,172.533 49.475,172.533 49.182,172.24 C117.1@49.182,170.944 ; v1(112.48,162.923) 112.482,162.922 112.482,161.94 120.172,154.25 120.703,154.25 122.067,155.614 123.899,155.614 124.449,156.164 C144.1@124.449,156.474 124.242,156.68 124.903,157.341 C144.1@124.903,158 ; C59.1@118.733,129.067 119.033,129.367 119.648,129.367 120.029,129.748 120.029,129.769 120.042,129.782 120.042,130.03 120.47,130.458 120.796,130.458 v1(120.798,130.459) ; v1(123,136) 121.75,137.25 121.75,153.5 123.5,155.25 ; v1(124.149,80.862) 124.151,80.864 124.151,80.869 124.648,81.367 128.094,81.367 134.519,74.942 142.474,74.942 148.416,69 v1(156.75,69) 159.5,71.75 v1(159.5,112.25) ; C115.1@131.866,158.148 132,158.282 v1(132,159.75) 129.05,159.75 128.05,158.75 126.065,158.75 125.315,158 C144.1@124.903,158 ; v1(132.925,137.607) 132.925,140.606 134.098,141.779 134.869,141.779 135.428,142.338 135.428,142.965 135.939,143.476 v1(135.939,143.478) ; v1(137.659,171.159) 137.657,171.157 137.657,170.401 133.103,165.846 J6.2@127.81,165.846 127.691,165.728 127.691,161.391 124.903,158.603 C144.1@124.903,158 ; FB4.1@150.676,118.19 151.833,118.19 R25.1@151.933,118.29 ; R25.1@152.164,118.336 152.164,119.561 152.852,120.248 152.998,120.248 v1(153,120.25) ; C5.1@163.146,157.278 163.696,157.828 C5.1@164.246,157.828 ; v1(164.278,159.536) 164.278,157.86 C5.1@164.246,157.828 ; C5.1@164.646,157.828 C5.1@164.246,157.828 ; v1(169.75,118.055) 169.75,114.45 172.2,112 172.2,98.3 177.8,92.7 221,92.7 224.223,89.477 224.223,68.711 226.761,66.173 v1(227.64,66.173) C20.1@228.703,66.173 ; C6.1@181.486,67.409 181.486,68.514 v1(181.799,68.828)
  Layer 2 w0.5: v1(54.749,163.26) 62.646,171.156 104.313,171.156 108.396,167.073 108.396,167.008 v1(112.48,162.923) ; v1(114.494,80.914) 115.408,80 123.287,80 v1(124.149,80.862)
  Bottom Layer w0.254: U15.44@113.287,80.906 113.291,80.91 114.49,80.91 v1(114.494,80.914) ; 181.837,68.241 181.837,67.555 U1.44@181.876,67.517 ; v1(227.64,66.173) 227.689,66.125 227.689,65.893 227.958,65.623 228.58,65.623 228.821,65.864 228.821,66.377 U4.44@228.919,66.475
  Bottom Layer w0.5: U10.44@119.364,130.421 v1@120.759,130.421 ; v1(120.798,130.459) 121.459,130.459 122.5,131.5 122.5,132.542 122.479,132.563 122.479,135.479 124.5,137.5 125.5,137.5 126,137 129.614,137 129.614,136.769 v1(129.615,136.768) 132.072,136.768 132.869,137.564 v1@132.908,137.564 ; v1@136.051,143.535 153,126.586 ; v1@137.659,171.161 137.659,172.734 138.053,173.128 150.686,173.128 v1(164.278,159.536) 166.538,159.536 168.409,157.665 168.409,121.973 169.75,120.632 v1(169.75,118.055) ; v1(150.178,55.495) 150.178,56.165 156.75,62.736 v1(156.75,69) 156.752,69.002 157.047,69.002 157.055,69.01 v1@174.685,69.01 ; v1(153,120.25) 153,126.586 ; v1(159.5,112.25) 159.5,115.436 156.468,118.468 156.468,123.118 153,126.586 ; v1@174.69,69.011 181.614,69.011 v1(181.799,68.828) 181.801,68.826 181.801,68.278 181.837,68.241
  other v1: 174.687,69.01
12V_SW1: C34.1 C37.2 C38.2 C40.1 C41.1 D6.1 R23.1 U6.28 U6.29 U7.44 | length 22.1
  Top Layer w0.254: C34.1@118.742,117.062 118.884,116.921 v1(120.437,116.921)
  Top Layer w0.5: v1(127.135,118.253) 127.137,118.255 128.03,118.255 C41.1@128.03,118.227 ; C41.1@128.23,118.274 128.23,116.77 128.64,116.36 128.64,116.345 128.847,116.137 D6.1@129,116.137 ; C41.1@128.609,118.174 C38.2@129.665,118.174 ; C38.2@129.665,118.249 129.665,118.224 129.89,117.999 131.095,117.999 C40.1@131.168,118.071 ; R23.1@131.18,116.278 131.174,116.284 131.174,118.065 C40.1@131.168,118.071 ; U6.28@134.674,118.116 132.799,118.116 C37.2@132.705,118.022 132.655,118.071 C40.1@131.168,118.071 ; U6.29@135.349,117.49 135.349,117.901
  Layer 2 w0.5: v1(120.437,116.921) 125.803,116.921 v1(127.135,118.253)
  Bottom Layer w0.254: U7.44@119.333,116.794 119.431,116.892 120.015,116.892
  Bottom Layer w0.5: 120.015,116.84 120.058,116.84 120.137,116.919 120.435,116.919 v1(120.437,116.921) ; v1(127.135,118.253) v1(127.135,118.253)
12V_SW2: C68.1 C71.2 C72.2 C74.1 C75.1 D9.1 R48.1 U11.28 U11.29 U12.44 | length 41.3
  Top Layer w0.254: D9.1@121.897,71.169 D9.1@121.917,71.15 ; C72.2@125.733,57.636 127.747,57.636 127.939,57.828 C71.2@128.972,57.828 129.178,57.828 130.373,57.828 130.918,57.283 ; C72.2@125.749,57.607 125.733,57.59 125.733,56.822 v1(126.143,56.412) ; R48.1@128.684,55.164 R48.1@128.719,55.129 ; R48.1@128.881,55.452 129.178,55.749 C71.2@129.178,57.815 ; 130.918,57.27 U11.28@132.737,57.27 U11.29@132.737,56.62
  Top Layer w0.5: C68.1@113.287,68.265 113.361,68.191 v1(114.62,68.191) ; D9.1@121.917,71.15 121.917,70.997 122.909,70.005 123.487,70.005 v1(123.489,70.003)
  Layer 2 w0.5: v1(114.62,68.191) 116.419,69.991 123.488,69.991 124.89,68.588 124.89,57.665 v1(126.143,56.412)
  Bottom Layer w0.254: U12.44@113.287,67.589 113.385,67.687 113.898,67.687 114.354,68.143 114.571,68.143 v1(114.62,68.191)
"BAT Bus+": J9.1 J10.1 K1.8 R43.1 R88.1 TP45.1
  other v1: 16.197,155.148 16.836,155.148 17.5,155.148
"BAT Bus-": J11.1 J12.1 K1.4 R2.1 R68.1 TP46.1
  other v1: 38.376,112.148 38.376,113.142 38.376,114.342 32.376,155.322 33.026,155.322 33.676,155.322
BatIN+: C60.2 C94.2 L9.1 L9.2 L9.3 L9.4 L13.5 L13.6 L13.7 L13.8 L18.1 L18.2 L18.3 L18.4
Batt_H1_Buff: J8.7 R37.1 | length 57
  Top Layer w0.254: v1(142.361,150.108) 142.361,147.889 149.25,141 149.25,127.149 148.351,126.25 R37.1@146.25,126.25
  Layer 2 w0.254: v1(142.361,150.108) 142.361,155.213 153.071,165.923 153.071,167.585 152.391,168.265 149.236,168.265 J8.7@148,167.03
Batt_H2_Buff: J8.11 R62.1 | length 143.7
  Top Layer w0.254: R62.1@143.538,65.069 146.319,65.069 147.75,66.5 157.5,66.5 160.7,69.7 160.7,136.18 155.431,141.449 155.431,141.464 155.391,141.504 155.245,141.504 v1(155.197,141.552)
  Layer 2 w0.254: J8.11@145.46,167.116 145.46,167.972 147.055,169.567 153.227,169.567 154.886,167.908 154.886,165.23 143.784,154.129 143.784,147.667 149.899,141.552 v1(155.197,141.552)
Batt_L1_Buff: J8.9 R40.1 | length 63.5
  Top Layer w0.254: R40.1@124,131 124,137.53 124.47,138 124.47,146.331 131.882,153.743 v1(143.118,153.743)
  Layer 2 w0.254: v1(143.118,153.743) 143.118,155.399 153.475,165.756 153.475,167.753 152.558,168.669 148.37,168.669 147.163,167.463 147.163,167.116 146.955,167.116 J8.9@146.788,166.949
Batt_L2_Buff: J8.13 R65.1 | length 139.8
  Top Layer w0.254: R65.1@119.843,80.611 119.868,80.611 122.71,83.452 145.252,83.452 156.5,94.7 156.5,134.403 145.375,145.527 145.375,147.776 144.994,148.157 v1(144.994,148.226)
  Layer 2 w0.254: J8.13@144.19,167.116 144.269,167.195 144.269,167.86 146.45,170.041 154.026,170.041 155.685,168.382 155.685,165.017 144.188,153.52 144.188,149.032 v1(144.994,148.226)
Boost1_IN+: C30.2 J2.1 L6.1 TP39.1
  other v1: 34.984,56.414 35.977,56.414 37.178,56.414 38.171,56.414 39.428,56.414 40.421,56.414 41.428,56.414 42.421,56.414 43.428,56.414 44.421,56.414 45.428,56.414 46.421,56.414 34.984,57.333 35.977,57.333 37.178,57.333 38.171,57.333 39.428,57.333 40.421,57.333 41.428,57.333 42.421,57.333 43.428,57.333 44.421,57.333 45.428,57.333 46.421,57.333
Boost2_IN+: C224.2 J5.1 L8.1 TP43.1
  other v1: 36.035,25.039 37.028,25.039 38.229,25.039 39.222,25.039 40.479,25.039 41.472,25.039 42.479,25.039 43.472,25.039 44.479,25.039 45.472,25.039 46.479,25.039 47.472,25.039 48.479,25.039
Boost_S1_Buff: J8.3 R1.1 | length 118
  Top Layer w0.254: J8.3@150.54,167.047 150.647,167.154 150.647,167.832 150.951,168.135 154.704,168.135 161.243,161.596 165.704,161.596 167.5,159.8 167.5,97 182.865,81.635 182.865,78.137 183.131,77.871 183.131,74.312 181.812,72.993 180.593,72.993 180.079,72.479 180.079,72.37 180.061,72.352 180.061,71.905 R1.1@179.801,71.645
Boost_S2_Buff: J8.5 R11.1 | length 162.8
  Top Layer w0.254: J8.5@149.27,167.116 149.27,168.028 149.842,168.6 154.811,168.6 161.411,162 166,162 167.977,160.023 167.977,122.552 170.75,119.78 170.75,114.45 172.8,112.4 172.8,99 178.5,93.3 222.31,93.3 225.404,90.206 225.404,71.6 225.966,71.037 225.966,70.364 226.017,70.312 R11.1@226.042,70.312
CS_Batt1+: J6.6 R66.1 | length 100.8
  Top Layer w0.254: R66.1@81.447,109.43 81.472,109.43 82.247,110.205 82.247,111.654 81.969,111.931 v1(81.969,112.975)
  Layer 2 w0.254: v1(81.969,112.975) 81.962,112.982 81.962,113.61 81,114.571 81,157.758 87.742,164.5 107.251,164.5 112.037,159.714 119.138,159.714 J6.6@125.27,165.846
CS_Batt1-: J6.8 R61.1 | length 98
  Top Layer w0.254: v1@81.383,113.258 81.383,111.151 R61.1@81.447,111.087
  Layer 2 w0.254: v1(81.373,113.264) 81.359,113.277 81.359,113.641 80.596,114.404 80.596,157.926 87.574,164.904 107.418,164.904 112.205,160.118 118.577,160.118 123.741,165.282 123.741,165.353 124,165.612 J6.8@124,165.846
CS_Batt2+: J6.14 R95.1 | length 134.6
  Top Layer w0.254: v1(79.881,72.65) 80.65,72.65 R95.1@80.8,72.5 ; v1(118.962,158.41) 118.962,163.82 120.19,165.048 J6.14@120.19,165.846
  Layer 2 w0.254: v1(79.881,72.65) 81.05,72.65 81.5,73.1 81.5,76.2 83.3,78 83.3,155.876 90.221,162.797 107.147,162.797 111.525,158.419 v1@118.953,158.419
CS_Batt2-: J6.16 R73.1 | length 131.2
  Top Layer w0.254: v1(80.8,74.9) 80.8,73.915 R73.1@80.815,73.9 ; v1(118.219,158.95) 117.87,159.299 117.87,164.796 J6.16@118.92,165.846
  Layer 2 w0.254: v1(80.8,74.9) 80.751,74.949 80.751,76.422 82.5,78.171 82.5,156.634 89.067,163.201 107.315,163.201 111.566,158.95 v1(118.219,158.95)
CS_Boost1+: C19.2 J6.7 R8.2 | length 191.4
  Top Layer w0.254: C19.2@129.5,162.7 129.6,162.6 v1(130.435,162.6) ; v1(170,113) 170,97.5 176.5,91 218.9,91 220.5,89.4 220.5,65.502 213.504,58.506 213.504,54.904 212,53.4 212,52.8 R8.2@211.9,52.7
  Bottom Layer w0.254: J6.7@124,167.116 124,168.138 124.623,168.761 128.79,168.761 130.5,167.051 130.5,162.844 130.484,162.828 130.484,162.649 v1(130.435,162.6) 130.435,161.889 130.069,161.523 130.069,153.631 158.794,124.906 158.794,121.603 167.397,113 v1(170,113)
